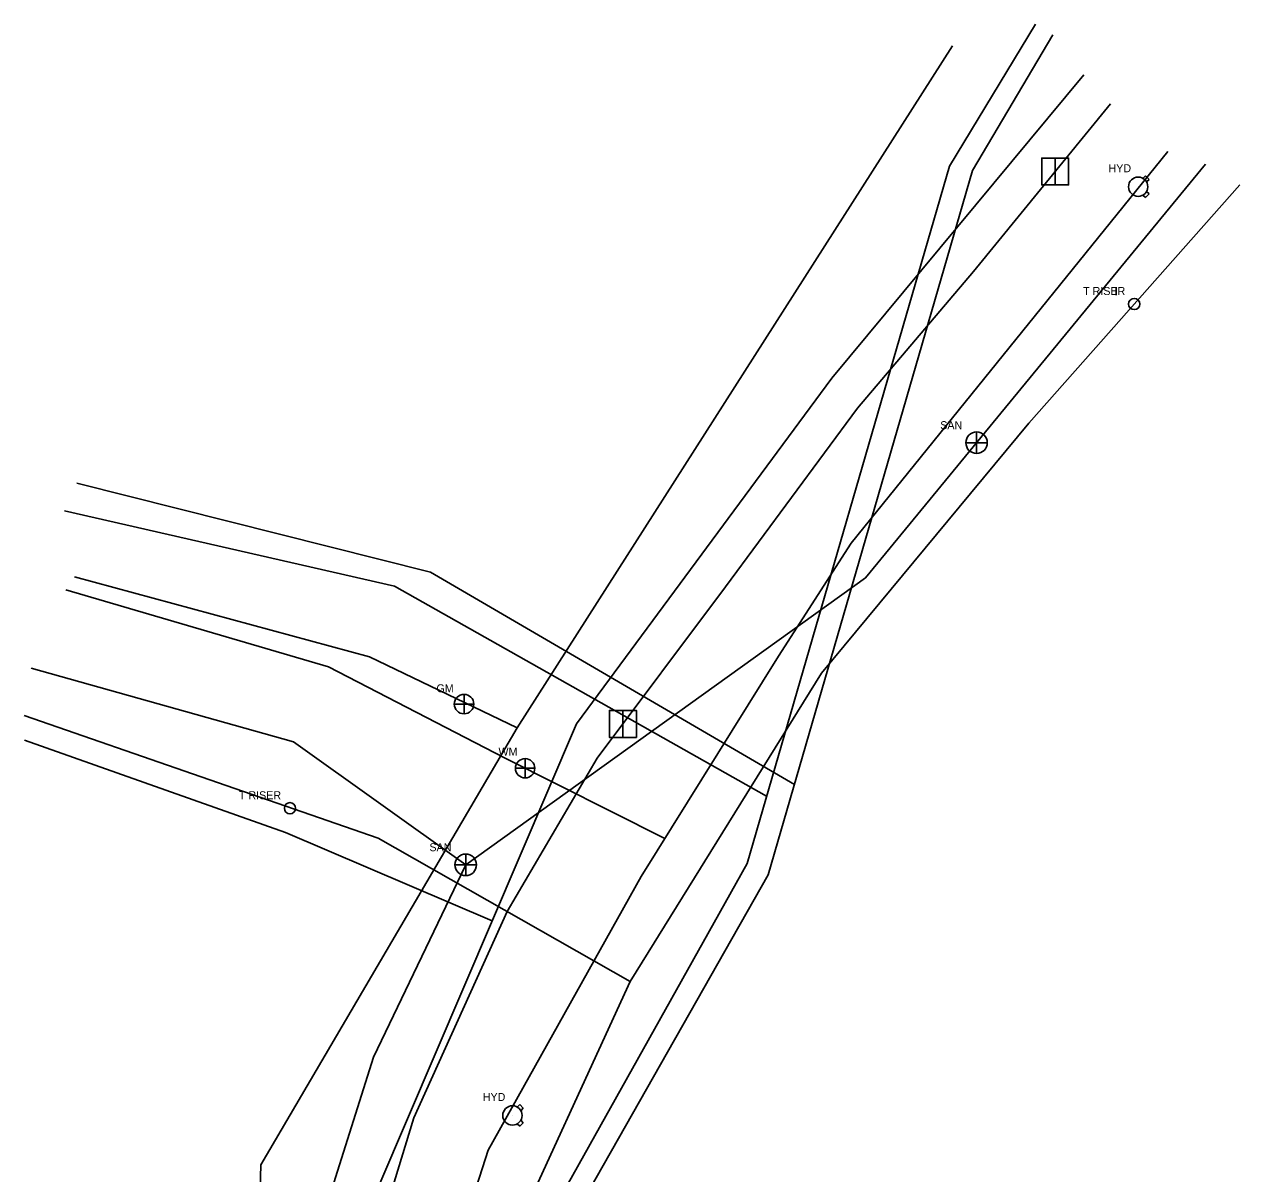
# Model space of a CAD drawing. Extents: x 551158 to 552108, y 1042267 to 1044064.
# Drawn here: x 551158 to 552108, y 1043165 to 1044064 of the extents above; entities that cross this region are included whole.
import ezdxf

# ---------------------------------------------------------------- set-up
doc = ezdxf.new("R2010")
doc.units = 0
for name, color, linetype in [('Common-Removals', 7, 'Continuous'), ('Utility-Cable', 7, 'Continuous'), ('Utility-Gas', 7, 'Continuous'), ('Utility-Pole', 7, 'Continuous'), ('Utility-Power', 7, 'Continuous'), ('Utility-Sanitary sewer', 7, 'Continuous'), ('Utility-Telephone', 7, 'Continuous'), ('Utility-Water', 7, 'Continuous')]:
    doc.layers.add(name, color=color, linetype=linetype)

msp = doc.modelspace()

# ---------------------------------------------------------------- linework, layer by layer
at = {"layer": 'Common-Removals'}
msp.add_line((552011.22, 1043852.15), (552011.22, 1043858.28), dxfattribs=at)
for points in [[(551418.21, 1042288.18), (551367.62, 1042533.64), (551357.31, 1042692.91), (551376.99, 1042872.8), (551415.4, 1043055.49), (551462.25, 1043209.14), (551535.32, 1043370.28), (551605.59, 1043490.2), (551705.83, 1043624.17), (551808.89, 1043763.77), (551899.77, 1043870.57), (552006.57, 1044001.74)], [(551561.23, 1042326.51), (551472.71, 1042711.13), (551472.71, 1042836.28), (551530.71, 1043095.75), (551631.44, 1043315.53), (551781.02, 1043556.68), (551942.8, 1043752.05), (552107.64, 1043938.25)], [(551631.44, 1043315.53), (551434.4, 1043427.7), (551158.02, 1043523.51)]]:
    msp.add_lwpolyline(points, dxfattribs=at)
msp.add_circle((552025.22, 1043845.15), 4.42, dxfattribs=at)
at = {"layer": 'Utility-Cable'}
for points in [[(551302.24, 1042271), (551477.71, 1042811.45), (551578.06, 1043148.89), (551722.69, 1043407.88), (551880.78, 1043952.78), (551948.05, 1044063.78)], [(551737.92, 1043460.37), (551447.36, 1043624.69), (551189.37, 1043683.39)]]:
    msp.add_lwpolyline(points, dxfattribs=at)
at = {"layer": 'Utility-Gas'}
for p, q in [((551501.6, 1043540.06), (551501.6, 1043532.45)), ((551501.65, 1043532.45), (551494.04, 1043532.45)), ((551501.6, 1043532.45), (551501.6, 1043532.45)), ((551501.6, 1043532.45), (551509.22, 1043532.45)), ((551501.6, 1043532.45), (551501.6, 1043524.89))]:
    msp.add_line(p, q, dxfattribs=at)
for points in [[(551883.28, 1044046.83), (551543.2, 1043513.97), (551342.83, 1043172.29), (551335.46, 1042901.45), (551202.12, 1042273.42)], [(551543.2, 1043513.97), (551427.71, 1043569.31), (551197.36, 1043632.03)]]:
    msp.add_lwpolyline(points, dxfattribs=at)
msp.add_circle((551501.6, 1043532.45), 7.61, dxfattribs=at)
msp.add_arc((551501.6, 1043532.45), 7.61, 0.00229, 90.00084, dxfattribs=at)
at = {"layer": 'Utility-Pole'}
for points in [[(551953, 1043938.25), (551963.5, 1043938.25), (551963.5, 1043959.25), (551953, 1043959.25)], [(551953, 1043959.25), (551974, 1043959.25), (551974, 1043938.25), (551953, 1043938.25)], [(551615.24, 1043506.44), (551625.74, 1043506.44), (551625.74, 1043527.45), (551615.24, 1043527.45)], [(551615.24, 1043527.45), (551636.25, 1043527.45), (551636.25, 1043506.44), (551615.24, 1043506.44)]]:
    msp.add_lwpolyline(points, close=True, dxfattribs=at)
at = {"layer": 'Utility-Power'}
for points in [[(551985.8, 1044024.18), (551789, 1043787.2), (551589.43, 1043516.95), (551413.43, 1043105.33), (551369.08, 1042629.97), (551424.51, 1042272.41)], [(551523.6, 1043362.99), (551362.16, 1043432), (551158.15, 1043504.15)]]:
    msp.add_lwpolyline(points, dxfattribs=at)
at = {"layer": 'Utility-Sanitary sewer'}
for p, q in [((551902.06, 1043728.41), (551902.06, 1043745.11)), ((551893.76, 1043736.71), (551910.46, 1043736.71)), ((551902.06, 1043736.71), (551902.06, 1043736.71)), ((551502.93, 1043398.5), (551502.93, 1043415.2)), ((551494.63, 1043406.8), (551511.33, 1043406.8)), ((551502.93, 1043406.8), (551502.93, 1043406.8))]:
    msp.add_line(p, q, dxfattribs=at)
for points in [[(551523.75, 1042314.92), (551354.03, 1042931.36), (551371.64, 1043069.06), (551430.88, 1043256.39), (551502.93, 1043406.9), (551815.16, 1043631.06), (552080.95, 1043954.5)], [(551502.93, 1043406.9), (551368.44, 1043502.97), (551163.49, 1043560.61)]]:
    msp.add_lwpolyline(points, dxfattribs=at)
for centre in [(551902.06, 1043736.71), (551502.93, 1043406.8)]:
    msp.add_circle(centre, 8.4, dxfattribs=at)
at = {"layer": 'Utility-Telephone'}
for points in [[(551317.6, 1042266.99), (551570.75, 1043053.4), (551593.86, 1043142.92), (551739.2, 1043398.96), (551898.99, 1043949.55), (551961.56, 1044055.43)], [(551759.71, 1043469.64), (551475.44, 1043635.57), (551199.12, 1043705.01)]]:
    msp.add_lwpolyline(points, dxfattribs=at)
for centre in [(552025.22, 1043845.15), (551365.61, 1043451.04)]:
    msp.add_circle(centre, 4.42, dxfattribs=at)
at = {"layer": 'Utility-Water'}
for p, q in [((552032.06, 1043943.38), (552033.99, 1043945.32)), ((552033.99, 1043945.32), (552036.83, 1043942.48)), ((552028.32, 1043936.81), (552028.32, 1043936.81)), ((552036.83, 1043942.48), (552034.89, 1043940.55)), ((552033.99, 1043928.31), (552032.06, 1043930.24)), ((552036.83, 1043931.14), (552033.99, 1043928.31)), ((552034.89, 1043933.07), (552036.83, 1043931.14)), ((551549.31, 1043489.86), (551549.31, 1043474.76)), ((551541.81, 1043482.26), (551556.91, 1043482.26)), ((551549.31, 1043482.26), (551549.31, 1043482.26)), ((551543.15, 1043217.48), (551545.07, 1043219.42)), ((551545.07, 1043219.42), (551547.92, 1043216.58)), ((551547.92, 1043216.58), (551545.97, 1043214.65)), ((551539.41, 1043210.91), (551539.41, 1043210.91)), ((551545.07, 1043202.41), (551543.15, 1043204.34)), ((551547.92, 1043205.24), (551545.07, 1043202.41)), ((551545.97, 1043207.17), (551547.92, 1043205.24))]:
    msp.add_line(p, q, dxfattribs=at)
for points in [[(552051.51, 1043964.34), (551804.17, 1043658.21), (551747.41, 1043570.02), (551639.96, 1043397.7), (551520.34, 1043183.81), (551478.78, 1043054.06), (551445.33, 1042879.71), (551429.11, 1042755.03), (551429.11, 1042586.76), (551455.47, 1042447.88), (551481.82, 1042296.84)], [(551190.53, 1043621.84), (551395.65, 1043561.66), (551533.22, 1043490.41), (551658.45, 1043427.35)]]:
    msp.add_lwpolyline(points, dxfattribs=at)
for centre in [(552028.32, 1043936.81), (551549.31, 1043482.26), (551539.41, 1043210.91)]:
    msp.add_circle(centre, 7.56, dxfattribs=at)

# ---------------------------------------------------------------- texts
at = {"layer": 'Common-Removals'}
msp.add_text('T RISER', height=6.251, dxfattribs=at).set_placement((551985.29, 1043852.16))
at = {"layer": 'Utility-Gas'}
msp.add_text('GM', height=6.251, dxfattribs=at).set_placement((551480.04, 1043541.64))
at = {"layer": 'Utility-Sanitary sewer'}
for p in [(551873.67, 1043747.32), (551474.55, 1043417.41)]:
    msp.add_text('SAN', height=6.251, dxfattribs=at).set_placement(p)
at = {"layer": 'Utility-Telephone'}
for p in [(551985.29, 1043852.16), (551325.68, 1043458.05)]:
    msp.add_text('T RISER', height=6.251, dxfattribs=at).set_placement(p)
at = {"layer": 'Utility-Water'}
for s, p in [('HYD', (552005.14, 1043948.13)), ('WM', (551528.49, 1043492.16)), ('HYD', (551516.23, 1043222.22))]:
    msp.add_text(s, height=6.251, dxfattribs=at).set_placement(p)

doc.saveas('drawing.dxf')
